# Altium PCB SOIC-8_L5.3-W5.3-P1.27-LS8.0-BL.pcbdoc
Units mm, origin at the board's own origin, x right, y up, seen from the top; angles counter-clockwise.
Board outline 18.16 x 22.01 mm, 2 copper layers (Top Layer, Bottom Layer), stack 0 mm thick; 1 components, 0 nets, 8 pads, 0 vias.
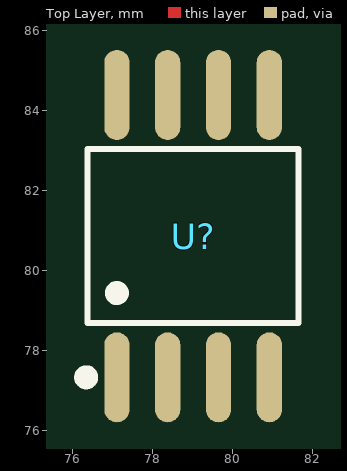
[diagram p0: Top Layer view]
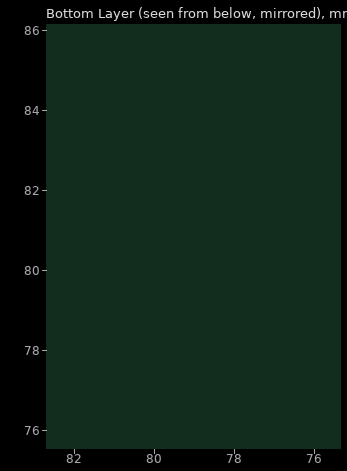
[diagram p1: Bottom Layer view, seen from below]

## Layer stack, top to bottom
Top Layer: signal copper (thickness not stored)
Bottom Layer: signal copper (thickness not stored)

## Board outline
88.011,69.85 69.85,69.85 69.85,91.86 88.011,91.86

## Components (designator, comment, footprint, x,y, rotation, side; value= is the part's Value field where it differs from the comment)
U? "" SOIC-8_L5.3-W5.3-P1.27-LS8.0-BL 79.022,80.855 r0 top

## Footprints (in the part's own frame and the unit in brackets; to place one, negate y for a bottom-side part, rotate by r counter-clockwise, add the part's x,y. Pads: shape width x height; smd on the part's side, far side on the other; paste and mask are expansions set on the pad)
SOIC-8_L5.3-W5.3-P1.27-LS8.0-BL [mm]
  oval 0.63x2.25 smd: 1(-1.905,-3.53) 2(-0.635,-3.53) 3(0.635,-3.53) 4(1.905,-3.53) 5(1.905,3.53) 6(0.635,3.53) 7(-0.635,3.53) 8(-1.905,3.53)
  silkscreen extent -2.82,-3.68 2.64,2.18

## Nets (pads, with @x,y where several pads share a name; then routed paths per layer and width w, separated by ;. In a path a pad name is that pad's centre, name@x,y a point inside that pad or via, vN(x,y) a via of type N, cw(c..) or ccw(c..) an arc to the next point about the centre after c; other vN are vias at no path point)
pads on no net: U?.1 U?.2 U?.3 U?.4 U?.5 U?.6 U?.7 U?.8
